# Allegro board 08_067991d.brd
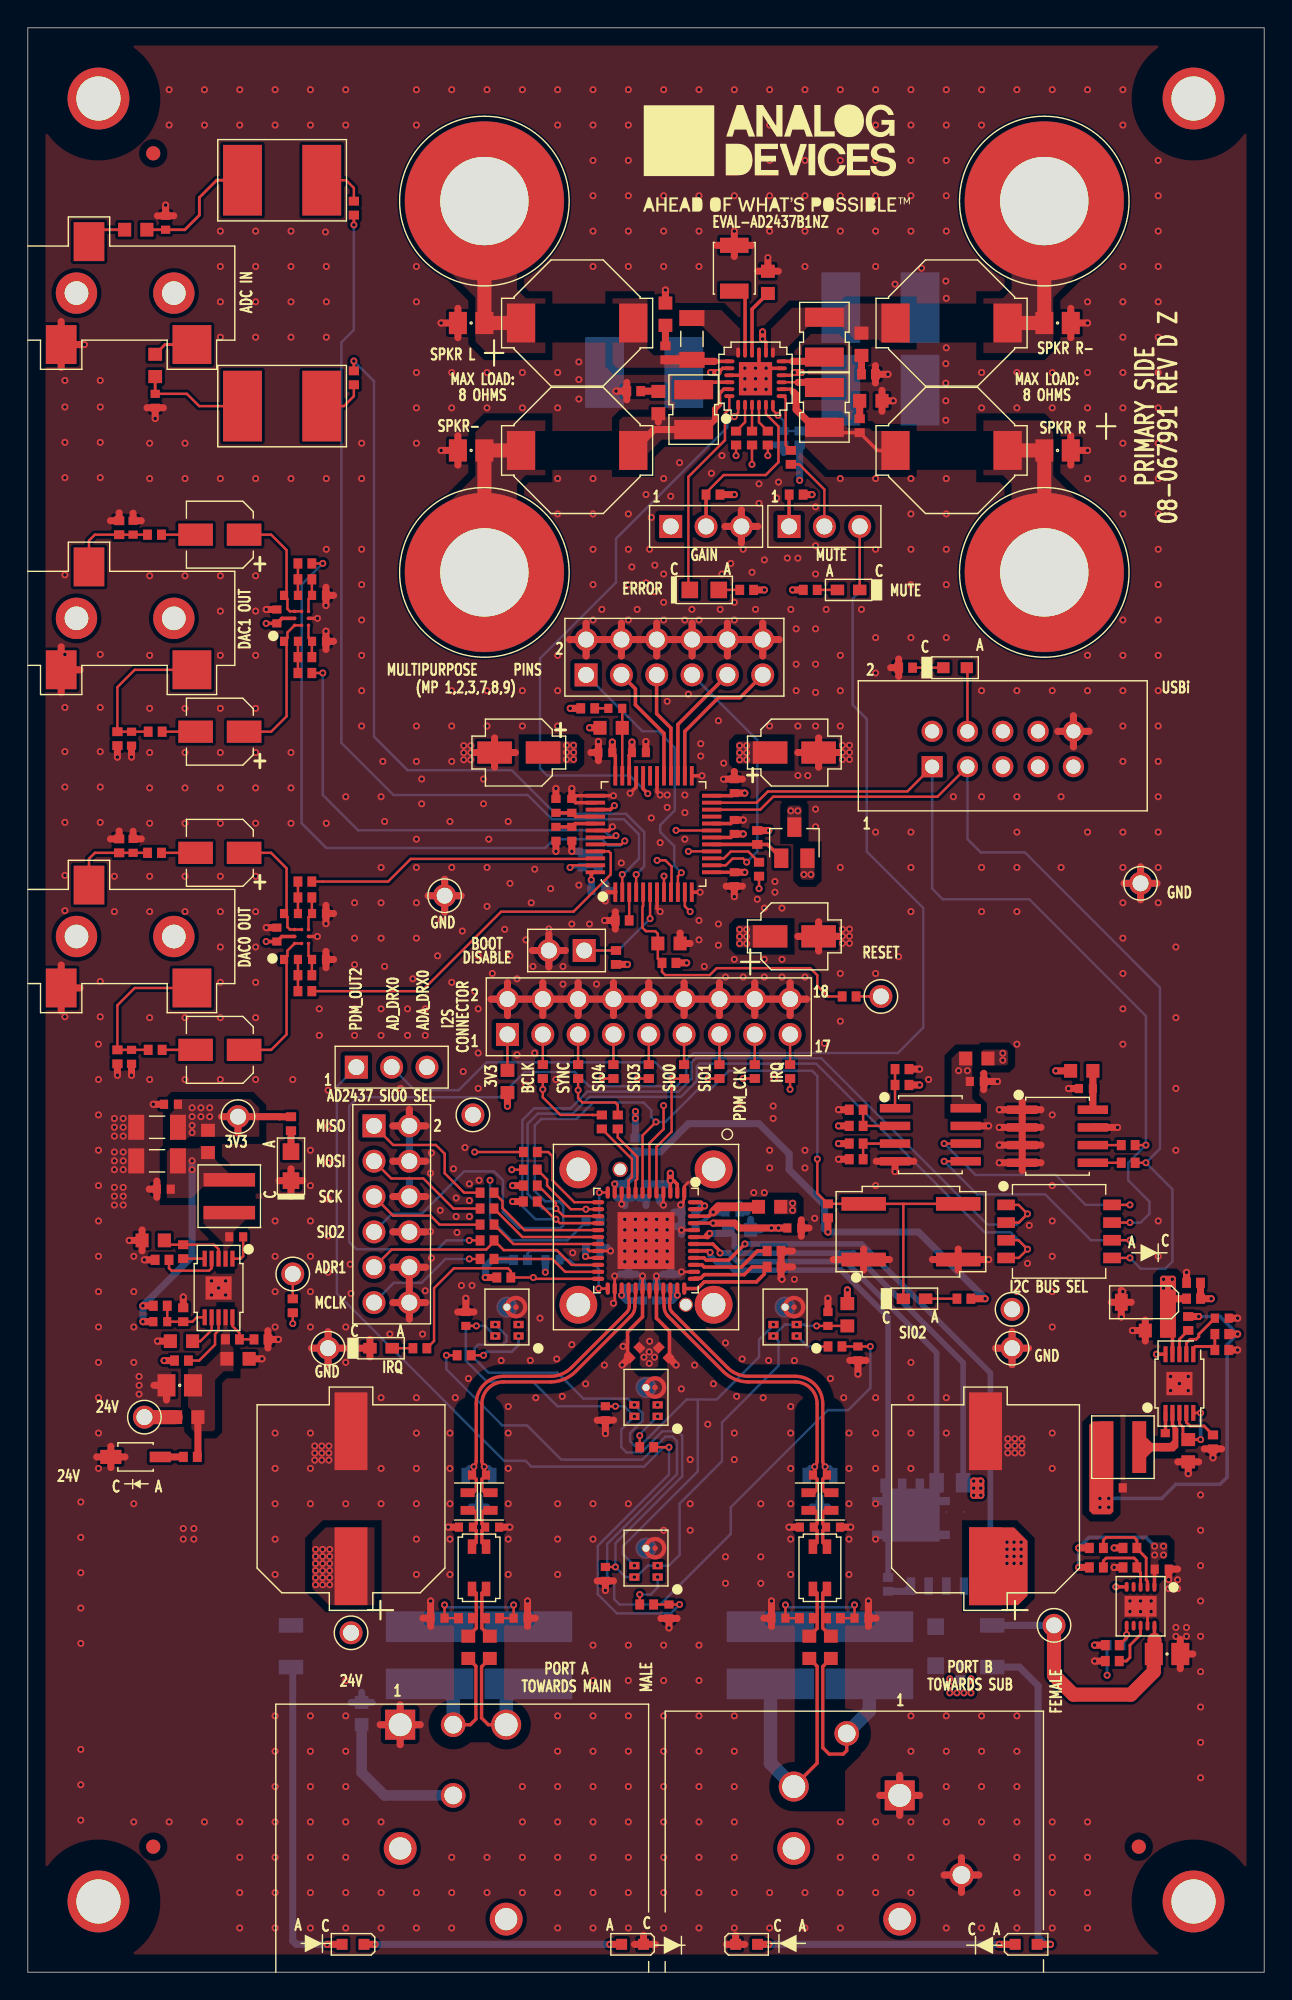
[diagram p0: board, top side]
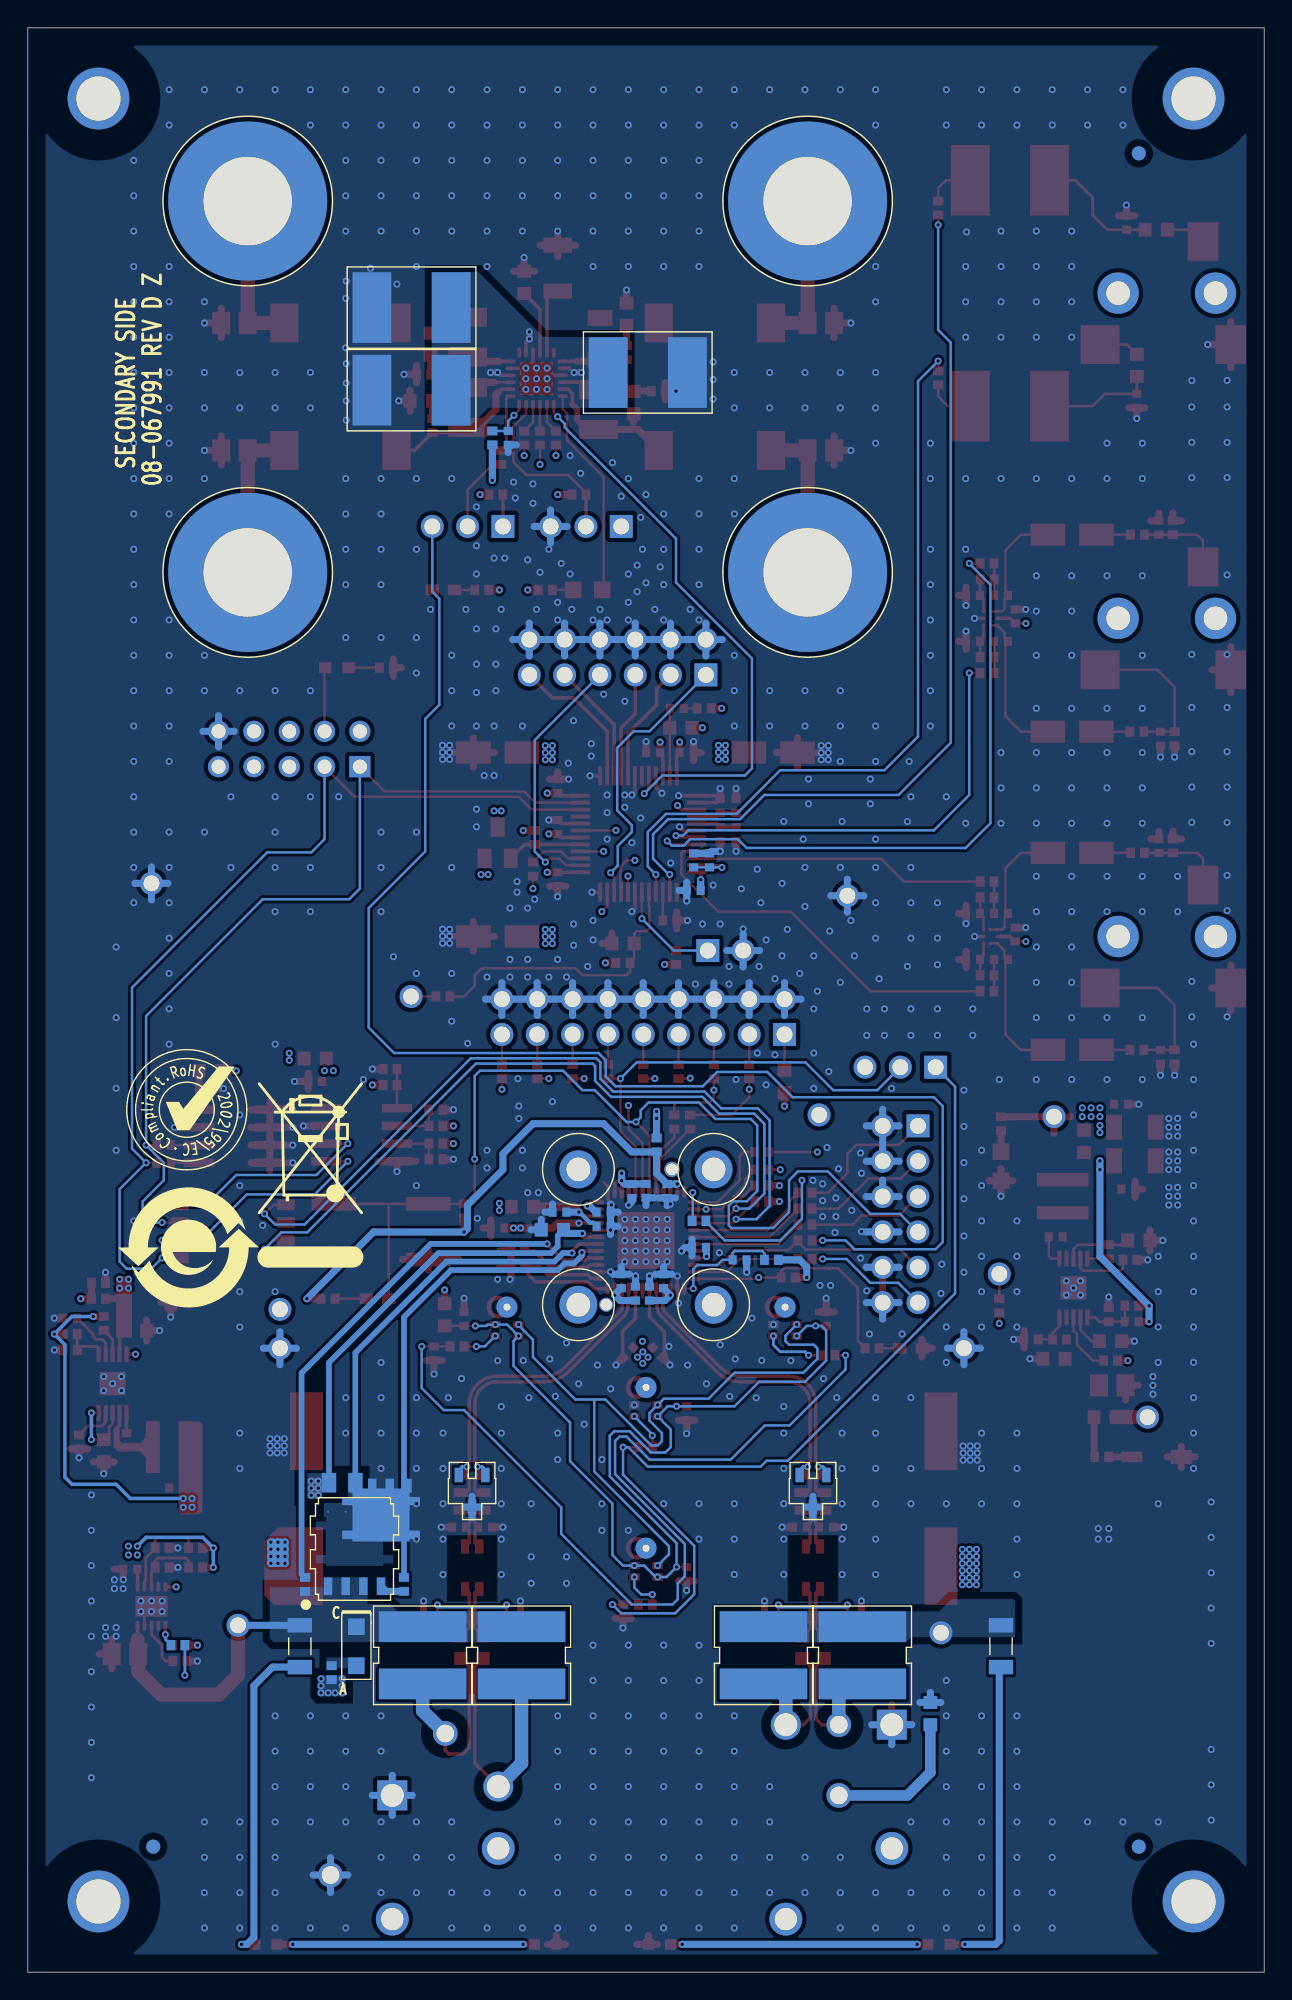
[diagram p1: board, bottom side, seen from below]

Outline 88.9 x 139.7 mm; copper layers: TOP, L2_GND, L3_PWR, L4_PWR, L5_GND, BOTTOM. Coordinates in mm from the lower left corner of the outline.
Outline path: 0,139.7 0,0 88.9,0 88.9,139.7 0,139.7

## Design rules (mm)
constraint set DEFAULT: min track width 0.178
net group APN: nets AN AP
net group BPN: nets BN BP
net group DP1: nets UNNAMED_3_CAP_I7_N1 UNNAMED_3_CAP_I8_N1
net group DP2: nets UNNAMED_3_CAP_I14_N1 UNNAMED_3_CAP_I15_N1
net group DP3: nets UNNAMED_3_CAP_I14_N2 UNNAMED_3_CAP_I15_N2
net group DP4: nets UNNAMED_4_CAP_I2_N1 UNNAMED_4_CAP_I3_N1
net group DP5: nets UNNAMED_4_CAP_I14_N1 UNNAMED_4_CAP_I16_N1
net group DP6: nets UNNAMED_4_CAP_I14_N2 UNNAMED_4_CAP_I16_N2

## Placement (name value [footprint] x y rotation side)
C1  10uF  [C0402]  44.45 56.13 270 bottom
C2  10NF  [C0402]  45.47 56.12 270 bottom
C3  0.1uF  [C0402]  40.64 52.07 0 bottom
C4  0.1uF  [C0402]  47.5 54.61 180 bottom
C5  0.1uF  [C0402]  42.93 56.12 270 bottom
C6  10NF  [C0402]  47.5 53.59 180 bottom
C7  0.1uF  [C0402]  50.67 54.61 0 bottom
C8  0.1uF  [C0603]  51.18 53.34 180 bottom
C9  10uF  [C0402]  55.12 53.47 0 top
C10  0.1uF  [C0402]  45.22 48.76 270 bottom
C11  10NF  [C0402]  45.72 44.52 315 top
C12  4.7uF  [C0402]  46.23 49.65 270 bottom
C13  0.1uF  [C0402]  43.62 44.52 225 top
C14  0.1uF  [C0402]  44.2 48.76 90 bottom
C15  4.7uF  [C0402]  43.18 49.65 90 bottom
C16  0.1uF  [C0402]  68.24 64 0 top
C17  12pF  [C0402]  32.44 35.72 180 top
C18  27pF  [C0402]  33.39 31.98 0 top
C19  27pF  [C0402]  31.5 31.98 180 top
C20  0.033uF  [C0402]  35.43 25.43 180 top
C21  0.033uF  [C0402]  29.46 25.43 180 top
C22  0.01uF  [C0603]  33.22 23.34 270 top
C23  0.01uF  [C0603]  31.67 23.34 270 top
C24  0.01uF  [C0603]  57.74 23.34 270 top
C25  12pF  [C0402]  56.96 35.72 0 top
C26  27pF  [C0402]  56.01 31.98 180 top
C27  27pF  [C0402]  57.9 31.98 0 top
C28  0.033uF  [C0402]  53.97 25.43 0 top
C29  0.033uF  [C0402]  59.94 25.43 0 top
C30  0.01uF  [C0603]  56.19 23.34 270 top
C31  3.3UF  [C1210H110]  47.88 112.27 270 top
C32  330uF  [CPLSMSQ512H650]  23.24 34.01 90 top
C33  330uF  [CPLSMSQ512H650]  68.86 34.01 90 top
C34  3.3UF  [C1210H110]  57.28 112.43 90 top
C35  10uF  [C2220-1]  44.32 114.94 180 bottom
C36  0.1uF  [C0402]  41.53 40.16 90 top
C37  0.1uF  [C0402]  57.53 46.93 270 top
C38  0.1uF  [C0402]  31.5 46.93 270 top
C39  0.1uF  [C0402]  41.53 28.61 270 top
C40  33pF  [C0402]  59.69 44.46 90 top
C41  33pF  [C0402]  46.1 25.92 90 top
C42  1uF  [C0603]  81.15 46.1 0 top
C43  150pF  [C0402]  20.94 76.06 0 top
C44  150pF  [C0402]  20.94 72.76 0 top
C45  470pF  [C0402]  18.92 76.06 180 top
C46  470pF  [C0402]  18.92 72.76 180 top
C47  100pF  [C0402]  9.91 125.69 90 top
C48  100pF  [C0402]  9.16 112.9 270 top
C49  10uF  [C2220-1]  18.28 128.75 180 top
C50  10uF  [C2220-1]  18.28 112.52 180 top
C51  47uF  [CPLSMSQ169H240]  13.81 80.42 180 top
C52  47uF  [CPLSMSQ169H240]  13.81 66.27 180 top
C53  1uF  [C0603]  83.44 37.46 270 top
C54  2.2NF  [C0402]  7.57 80.92 90 top
C55  2.2NF  [C0402]  7.46 65.77 270 top
C56  0.1uF  [C0402]  17.91 74.55 270 top
C57  150pF  [C0402]  20.94 98.92 0 top
C58  150pF  [C0402]  20.94 95.62 0 top
C59  470pF  [C0402]  18.92 98.92 180 top
C60  470pF  [C0402]  18.92 95.62 180 top
C61  47uF  [CPLSMSQ169H240]  13.81 103.28 180 top
C62  47uF  [CPLSMSQ169H240]  13.81 89.13 180 top
C63  0.1uF  [C0402]  17.91 97.41 270 top
C64  2.2NF  [C0402]  7.57 103.78 90 top
C65  2.2NF  [C0402]  7.46 88.63 270 top
C66  10uF  [C2220-1]  61.31 113.66 0 bottom
C67  3.3UF  [C1210H110]  57.28 117.47 270 top
C68  680pF  [C0603]  45.34 112.78 270 top
C69  680pF  [C0603]  45.85 119.13 90 top
C70  3.3uF  [C1206]  47.75 117.35 270 top
C71  680pF  [C0603]  59.94 116.96 90 top
C72  680pF  [C0603]  60.62 112.9 0 top
C73  10UF  [C1210-2]  50.8 122.43 270 top
C74  10uF  [C2220-1]  61.31 119.6 180 bottom
C75  0.68uF  [C0805H60]  31.88 109.34 180 top
C76  0.68uF  [C0805H60]  31.88 118.49 0 top
C77  0.68uF  [C0805H60]  74.04 118.49 0 top
C78  0.68uF  [C0805H60]  74.04 109.34 180 top
C79  0.1uF  [C0603]  53.21 121.41 90 top
C80  1uF  [C0603]  46.1 73.91 180 top
C81  0.1uF  [C0402]  37.72 51.18 180 bottom
C82  10NF  [C0402]  85.85 46.99 0 top
C83  10UF  [CPLSMSQ169H217]  55.12 87.63 0 top
C84  10UF  [CPLSMSQ169H217]  35.31 87.63 180 top
C85  0.1uF  [C0402]  41.02 79.88 90 bottom
C86  0.1uF  [C0402]  50.8 82.28 90 top
C87  10uF  [C0402]  39.88 79.88 90 bottom
C88  0.1uF  [C0402]  41.02 77.72 0 bottom
C89  0.1uF  [C0402]  39.12 83.8 90 top
C90  0.1uF  [C0402]  41.53 87.63 180 top
C91  10uF  [C0402]  37.97 83.8 90 top
C92  0.1uF  [C0402]  43.94 87.63 0 top
C93  10UF  [CPLSMSQ169H217]  55.12 74.42 0 top
C94  0.1uF  [C0402]  50.8 78.53 270 top
C95  0.056uF  [C0402]  42.24 90.8 180 top
C96  0.1uF  [C0402]  50.8 85.22 90 top
C97  3.3NF  [C0603]  41.94 89.41 180 top
C98  10uF  [C0402]  37.97 81.79 270 top
C99  0.1uF  [C0402]  39.12 81.79 270 top
C100  0.1uF  [C0402]  76.08 63.49 0 top
C101  4.7uF  [C0805H60]  10.92 42.16 180 top
C102  0.1uF  [C0603]  15.11 44.07 0 top
C103  1uF  [C0603]  9.02 52.58 180 top
C104  0.01uF  [C0603]  11.05 45.34 0 top
C105  0.1uF  [C0402]  14.99 52.83 0 top
C106  10uF  [C0402]  9.78 56.26 180 top
C107  10pF  [C0402]  9.53 46.74 0 top
C108  22uF  [C1206]  9.29 58.29 180 top
C109  22uF  [C1206]  9.29 60.71 180 top
C110  0.1uF  [C0402]  10.29 62.36 180 top
C114  0.1uF  [C0402]  81.79 38.23 270 top
C115  10uF  [C0402]  78.23 34.8 0 top
C116  1uF  [C0402]  81.53 28.96 0 top
C117  4.7uF  [C0805H60]  81.91 22.86 180 top
C118  0.1uF  [C0402]  54.36 110.24 270 bottom
C123  0.01uF  [C0603]  24 18.58 270 bottom
D1  PMEG6010CEH,115  [SOD123F]  65.28 23.42 270 bottom
D2  BZT52C27-7-F  [SOD123-2]  80.26 48.13 180 top
D4  TPD2E2U06QDBZRQ1  [SOT23_B]  56.96 34.57 0 bottom
D6  TPD2E2U06QDBZRQ1  [SOT23_B]  32.44 34.57 0 bottom
DS1  SML-LXT0805GW-TR  [LXT0805]  18.92 57.91 90 top
DS2  APT1608LVBC/D  [LED0603]  25.4 44.83 0 top
DS3  APT1608LVBC/D  [LED0603]  63.75 48.39 0 top
DS4  LB L293-N1N2-25-Z(blue)  [LED0603-2]  23.39 2 180 top
DS5  SML-E12M8WT86  [LED0603_A]  66.67 93.73 0 top
DS6  APT1608LVBC/D  [LED0603]  59.02 99.31 180 top
DS8  LB L293-N1N2-25-Z(blue)  [LED0603-2]  43.49 2 180 top
DS9  LB L293-N1N2-25-Z(blue)  [LED0603-2]  71.78 2 0 top
DS10  CMD28-21VGC/TR8  [LEDCMD28-21B]  7.75 37.02 0 top
DS11  SML-LXT0805YW-TR  [LXT0805]  48.64 99.31 0 top
DS12  LB L293-N1N2-25-Z(blue)  [LED0603-2]  51.68 2 0 top
E1  600OHMS  [L0603]  34.49 64 270 top
E3  600OHMS  [L0603]  53.34 54.99 180 top
E4  600OHMS  [L0603]  68.24 65.65 180 top
E5  600OHMS  [L0603]  58.93 47.23 90 top
E9  600OHMS  [L0603]  7.76 125.19 0 top
E10  600OHMS  [L0603]  9.16 115.44 270 top
E11  600OHMS  [L0603]  75.78 64.76 0 top
E12  470OHM AT 100MEGHZ  [L0603]  12.95 59.69 90 top
E14  600OHMS  [L0603]  11.43 39.88 180 top
FL1  ACT1210L-101-2P-TL00  [FLSML154W98H98]  32.44 29.05 270 top
FL2  ACT1210L-101-2P-TL00  [FLSML154W98H98]  56.96 29.05 270 top
JP1  TSW-103-07-G-S  [CNTHMHDR1X3L300W98H343]  23.62 65.02 0 top
JP2  TSW-103-07-G-S  [CNTHMHDR1X3L300W98H343]  46.23 103.88 0 top
JP3  TSW-103-07-G-S  [CNTHMHDR1X3L300W98H343]  54.74 103.88 0 top
L1  180nH  [L7144]  33.27 33.82 270 top
L2  180nH  [L7144]  31.62 33.82 270 top
L3  180nH  [L7144]  56.13 33.82 270 top
L4  180nH  [L7144]  57.78 33.82 270 top
L5  15uH  [INDSUMCDRH8D43]  39.5 109.34 180 top
L6  15uH  [INDSUMCDRH8D43]  39.5 118.49 180 top
L7  4.7uH  [LSMSQ228H118]  36 22.77 90 bottom
L8  4.7uH  [LSMSQ228H118]  28.89 22.77 90 bottom
L9  15uH  [INDSUMCDRH8D43]  66.42 118.49 0 top
L10  15uH  [INDSUMCDRH8D43]  66.42 109.34 0 top
L11  4.7uH  [LSMSQ228H118]  53.4 22.77 90 bottom
L12  4.7uH  [LSMSQ228H118]  60.51 22.77 90 bottom
L13  10uH  [LSMSQ157H161]  14.49 55.75 90 top
L14  10uH  [LSMSQ157H161]  78.74 37.72 180 top
NOREF  -  []  -105.41 -135.39 0 top
NOREF#2  -  [unnamed#2]  5.08 5.08 0 top
NOREF#3  -  []  0 0 0 top
NOREF#4  -  [unnamed#2]  49.31 57.68 270 top
NOREF#5  -  [unnamed#2]  39.59 57.68 270 top
NOREF#6  -  []  -105.41 -135.39 0 top
NOREF#7  -  [unnamed#2]  39.59 47.96 270 top
NOREF#8  -  []  69.91 130.99 0 top
NOREF#9  -  [unnamed#2]  79.88 9.02 180 top
NOREF#10  -  []  15.88 210.95 0 top
NOREF#11  -  []  88.9 0 90 top
NOREF#12  -  []  -44.45 235.45 0 top
NOREF#13  -  []  88.9 0 0 top
NOREF#14  -  [unnamed#2]  9.02 9.02 90 top
NOREF#15  -  []  -105.41 -135.39 0 top
NOREF#16  -  []  -12.95 94.11 0 top
NOREF#17  -  []  -85.28 13.58 0 top
NOREF#18  -  []  15.75 206.76 0 top
NOREF#19  -  []  0 139.7 0 top
NOREF#20  -  []  5.08 5.08 0 top
NOREF#21  -  [unnamed#2]  49.31 47.96 270 top
NOREF#22  -  []  0 0 0 top
NOREF#23  -  []  45.97 41.27 0 top
NOREF#24  -  [unnamed#2]  83.82 134.62 0 top
NOREF#25  -  [unnamed#2]  83.82 5.08 0 top
NOREF#26  -  []  0 139.7 0 top
NOREF#27  -  []  15.59 15.24 0 top
NOREF#28  -  []  81.66 19.93 0 top
NOREF#29  -  []  53.86 130.31 0 top
NOREF#30  -  []  164.72 123.94 0 top
NOREF#31  -  [unnamed#2]  47.31 47.96 270 top
NOREF#32  -  [unnamed#2]  9.02 130.68 0 top
NOREF#33  -  []  27.79 183.9 0 top
NOREF#34  -  [unnamed#2]  42.59 57.68 270 top
NOREF#35  -  []  153.42 178.93 0 top
NOREF#36  -  []  -105.41 -135.39 0 top
NOREF#37  -  []  5.08 5.08 0 top
NOREF#38  -  [unnamed#2]  5.08 134.62 0 top
NOREF#39  -  []  275.59 329.43 0 top
NOREF#40  -  []  77.34 52.07 180 bottom
NOREF#41  -  [unnamed#2]  9.02 9.02 270 bottom
NOREF#42  -  []  77.47 61.97 180 bottom
NOREF#43  -  []  59.31 67.51 180 bottom
NOREF#44  -  [unnamed#2]  79.88 9.02 0 bottom
NOREF#45  -  [unnamed#2]  9.02 130.68 180 bottom
P1  NC3MAH-LR  [CNNEUTRIK-NC3MAH-LR]  26.78 17.78 0 top
P2  TSW-109-07-G-D  [CNTHMHDR2X9L900W200H343]  34.49 67.37 0 top
P4  SJ-3523-SMT  [CNCUISJ-3523-SMT]  7 120.64 0 top
P5  TSW-106-07-G-D  [CNHDR2X6H330]  40.14 93.21 0 top
P6  SJ-3523-SMT  [CNCUISJ-3523-SMT]  7 74.41 0 top
P7  SJ-3523-SMT  [CNCUISJ-3523-SMT]  7 97.27 0 top
P9  TSW-101-07-G-D  [CNHDR2X1H428]  40 73.41 90 top
P10  N2510-6002-RB  [CN3MN2510-6002RB]  65.02 86.61 0 top
P13  NC3FAH2-LR-DAE  [CNNEUTRIK-NC3FAH2]  62.69 12.7 180 top
P15  TSW-106-07-G-D  [CNHDR2X6H330]  24.89 60.81 270 top
P16  111-2223-001  [CNEMERSON111-2223-001]  32.83 100.57 90 top
P17  111-2223-001  [CNEMERSON111-2223-001]  32.83 127.25 90 top
P18  111-2223-001  [CNEMERSON111-2223-001]  73.09 127.25 90 top
P19  111-2223-001  [CNEMERSON111-2223-001]  73.09 100.57 90 top
Q1  DMTH8012LPSQ-13  [POWERDI5060-8]  65.41 30.4 180 bottom
Q2  ZXTP25040DFLTA  [SOT23]  55.12 81.15 0 top
R1  0  [R0402]  37.03 64.71 270 top
R2  0  [R0402]  39.57 64.71 270 top
R3  0  [R0402]  42.11 64.71 270 top
R4  0  [R0402]  44.65 64.71 270 top
R5  0  [R0402]  47.19 64.71 270 top
R6  0  [R0402]  49.73 64.71 270 top
R7  0  [R0402]  52.27 64.71 270 top
R8  0  [R0402]  54.81 64.71 270 top
R9  49.9  [R0402]  42.42 61.09 270 top
R10  49.9  [R0402]  41.27 61.09 270 top
R11  49.9  [R0402]  33.02 51.24 0 top
R12  49.9  [R0402]  40.64 53.98 0 bottom
R14  49.9  [R0402]  36.13 57.66 0 top
R15  49.9  [R0402]  36.13 58.93 0 top
R16  330  [R0402]  18.92 60.96 270 top
R17  10K  [R0402]  34.23 49.91 0 top
R18  100K  [R0402]  53.66 50.67 0 top
R19  100K  [R0402]  53.66 51.82 0 top
R20  3.32K  [R0402]  28.19 44.83 180 top
R21  3.32K  [R0402]  67.31 48.39 180 top
R22  10K  [R0402]  62.86 63.74 180 top
R23  10K  [R0402]  62.86 64.89 0 top
R24  10K  [R0402]  59.56 60.8 0 top
R25  10K  [R0402]  59.56 61.97 180 top
R26  10K  [R0402]  57.53 54.7 90 top
R27  10K  [R0402]  59.56 59.53 0 top
R28  10K  [R0402]  59.56 58.41 180 top
R29  113  [R0402]  33.42 25.43 0 top
R30  113  [R0402]  31.47 25.43 0 top
R31  113  [R0402]  55.98 25.43 180 top
R32  113  [R0402]  57.93 25.43 180 top
R33  0  [R0402]  61.85 27.86 270 bottom
R34  0  [R0402]  68.97 27.86 270 bottom
R35  0.05  [R0805]  66.3 35.17 180 bottom
R36  1.78K  [R1206]  69.34 23.42 90 bottom
R37  33  [R0402]  58.04 44.96 0 top
R38  33  [R0402]  31.37 44.32 180 top
R39  33  [R0402]  44.5 26.42 0 top
R40  33  [R0402]  44.5 37.72 0 top
R41  4.75K  [R0402]  19.92 78.36 180 top
R42  4.75K  [R0402]  19.92 70.48 180 top
R43  4.75K  [R0402]  19.92 77.22 0 top
R44  4.75K  [R0402]  19.92 71.63 0 top
R45  18.2K  [R0402]  23.44 126.75 270 top
R46  18.2K  [R0402]  23.44 114.55 90 top
R47  604  [R0402]  9.11 80.42 180 top
R48  604  [R0402]  9.16 66.27 180 top
R49  49.9K  [R0402]  6.57 80.92 90 top
R50  49.9K  [R0402]  6.44 65.77 270 top
R51  4.75K  [R0402]  19.92 101.22 180 top
R52  4.75K  [R0402]  19.92 93.34 180 top
R53  4.75K  [R0402]  19.92 100.08 0 top
R54  4.75K  [R0402]  19.92 94.49 0 top
R55  604  [R0402]  9.11 103.28 180 top
R56  604  [R0402]  9.16 89.13 180 top
R57  49.9K  [R0402]  6.57 103.78 90 top
R58  49.9K  [R0402]  6.44 88.63 270 top
R59  0  [R0402]  53.21 110.23 90 top
R60  5.6  [R0402]  43.57 113.6 0 top
R61  5.6  [R0402]  45.85 116.35 90 top
R62  5.6  [R0402]  60.44 114.81 180 top
R63  47K  [R0402]  49.27 106.16 180 top
R64  330  [R0402]  51.69 99.31 180 top
R65  1K  [R0402]  55.24 106.16 180 top
R66  0  [R0402]  54.86 108.84 90 top
R67  0  [R0402]  50.93 110.23 90 top
R68  0  [R0402]  52.07 110.23 90 top
R69  18.2K  [R0402]  42.74 75.56 0 top
R70  49.9  [R0402]  52.58 79.25 90 top
R71  475  [R0402]  40.26 90.8 180 top
R72  1K  [R0402]  52.45 81.53 90 top
R73  10K  [R0402]  42.29 72.91 270 top
R74  0  [R0402]  79.12 59.43 0 top
R75  0  [R0402]  79.12 58.16 0 top
R76  5.6  [R0402]  59.82 111.11 90 top
R77  1K  [R0402]  63.12 93.73 180 top
R78  2K  [R0402]  36.13 56.52 0 top
R79  162K  [R0402]  14.72 45.47 180 top
R80  10K  [R0402]  16.76 45.47 0 top
R81  0  [R0402]  11.18 51.77 270 top
R82  71.5K  [R0402]  9.65 51.18 180 top
R83  10K  [R0402]  11.05 43.94 0 top
R84  1MEG  [R0402]  9.53 47.88 0 top
R85  309K  [R0402]  11.18 47.24 270 top
R86  2K  [R0402]  36.13 55.37 0 top
R87  100  [R0402]  19.05 47.88 90 top
R88  100  [R0402]  59.05 70.1 0 top
R91  1.78K  [R1206]  18.92 23.42 90 bottom
R95  3.32K  [R0402]  56.26 99.31 0 top
R96  100  [R0402]  67.06 21.52 90 bottom
R97  10K  [R0402]  35.43 51.18 0 bottom
R98  10K  [R0402]  46.1 72.52 0 top
R99  10K  [R0402]  55.5 110.24 90 bottom
R100  0  [R0402]  33.02 56.01 180 top
R101  0  [R0402]  33.02 54.86 180 top
R102  0  [R0402]  33.02 53.71 180 top
R103  0  [R0402]  33.02 52.58 180 top
R104  0  [R0402]  43.69 59.44 270 bottom
R105  100K  [R0402]  83.82 48.39 0 top
R106  10K  [R0402]  83.82 49.53 180 top
R107  18.2K  [R0402]  85.22 38.1 90 top
R108  100K  [R0402]  85.85 45.85 180 top
R109  18.7K  [R0402]  85.85 44.7 180 top
R110  100K  [R0402]  83.44 46.61 270 top
R111  2.2MEG  [R0402]  76.83 30.48 180 top
R112  1.5MEG  [R0402]  79.25 30.48 0 top
R113  2.2MEG  [R0402]  76.83 29.08 180 top
R114  499K  [R0402]  79.25 29.08 0 top
R115  10K  [R0402]  77.98 23.49 0 top
R116  3.01K  [R0402]  77.98 22.35 0 top
R117  10K  [R0402]  78.11 23.49 180 bottom
R151  2.4K  [R0402]  11.68 37.02 180 top
S1  TDA04H0SB1  [SWSMDIP8H91]  74.15 53.22 270 top
S2  EVQQ2K03W  [SWSML260W236H130]  63.5 53.2 0 top
TP1  TESTPAD  [TPC65D45]  23.24 24.38 0 top
TP2  TESTPAD  [TPC65D45]  8.38 39.88 0 top
TP3  TESTPAD  [TPC65D45]  32 61.59 0 top
TP4  TESTPAD  [TPC65D45]  70.77 47.62 0 top
TP5  TESTPAD  [TPC65D45]  21.59 44.83 0 top
TP6  TESTPAD  [TPC65D45]  70.77 44.83 0 top
TP7  TESTPAD  [TPC65D45]  29.97 77.34 0 top
TP8  TESTPAD  [TPC65D45]  80.01 78.23 0 top
TP9  TESTPAD  [TPC65D45]  15.11 61.47 270 top
TP10  TESTPAD  [TPC65D45]  19.05 50.16 0 top
TP11  TESTPAD  [TPC65D45]  73.79 24.92 0 top
TP12  TESTPAD  [TPC65D45]  61.34 70.1 0 top
U1  MMICT3902-00-012  [LGA_CAV5_MEMS]  54.45 47.07 90 top
U2  MMICT3902-00-012  [LGA_CAV5_MEMS]  34.45 47.07 90 top
U3  MMICT3902-00-012  [LGA_CAV5_MEMS]  44.45 29.75 90 top
U4  MMICT3902-00-012  [LGA_CAV5_MEMS]  44.45 41.3 90 top
U5  LT8609EMSE#TRPBF  [MSOP10_PAD1_88X1_68]  13.72 49.16 180 top
U7  AD8606ACBZ  [WLCSP8]  19.68 74.41 0 top
U8  LT8606IMSE#PBF  [MSOP10_PAD1_88X1_68]  82.8 42.29 0 top
U9  AD8606ACBZ  [WLCSP8]  19.68 97.27 0 top
U10  MAX17612AATB+  [DFN10_3X3_PAD2_3X1_5]  80.01 26.29 180 top
U11  AD2437  [QFN48_7X7_PAD4_1X4_1]  44.45 52.57 180 top
U12  ADAU1701JSTZ  [48LQFP]  44.99 81.78 0 top
U14  M24512-RMN6TP  [SO8]  64.9 60.17 270 top
U15  M24512-RMN6TP  [SO8]  74.04 60.06 270 top
U16  BD28623MUV-E2  [QFN24_4X4_PAD2_4X2_4]  52.32 114.49 0 top

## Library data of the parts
C1 C9 C87 C91 C98 C106 C115 = CAP: User Part Number: UPN; Tolerance: 20; alternate symbols: (C0402L); part number: CAP_SM-10UF,10V,20,E020928,C0402; tolerance: 20
C2 C6 C11 C82 = CAP: User Part Number: UPN; Tolerance: 10; alternate symbols: (C0402L); part number: CAP_SM-10NF,25V,10,E046235,C0402; tolerance: 10
C3-C5 C7 C10 C13 C14 C16 C36-C39 C56 C63 C81 C85 C86 C88-C90 C92 C94 C96 C99 C100 C105 C110 C114 C118 = CAP: User Part Number: UPN; Tolerance: 10; alternate symbols: (C0402L); part number: CAP_SM-0.1UF,25V,10,E025708,C0402; tolerance: 10
C8 C79 C102 = CAP: User Part Number: UPN; Tolerance: 10; alternate symbols: (C0603L); part number: CAP_SM-0.1UF,50V,10,E011865,C0603; tolerance: 10
C12 C15 = CAP: User Part Number: UPN; Tolerance: 20; alternate symbols: (C0402L); part number: CAP_SM-4.7UF,6.3V,20,E014207,C0402; tolerance: 20
C17 C25 = CAP: User Part Number: UPN; Tolerance: 5; alternate symbols: (C0402L); part number: CAP_SM-12PF,50V,5,E034633,C0402; tolerance: 5
C18 C19 C26 C27 = CAP: User Part Number: UPN; Tolerance: 5; alternate symbols: (C0402L); part number: CAP_SM-27PF,50V,5,E033384,C0402; tolerance: 5
C20 C21 C28 C29 = CAP: User Part Number: UPN; Tolerance: 10; alternate symbols: (C0402L); part number: CAP_SM-0.033UF,50V,10,E019776,C0402; tolerance: 10
C22-C24 C30 C104 = CAP: User Part Number: UPN; Tolerance: 10; alternate symbols: (C0603L); part number: CAP_SM-0.01UF,50V,10,E000421,C0603; tolerance: 10
C31 C34 C67 = CAP: Tolerance: 20; User Part Number: UPN; alternate symbols: (); part number: CAP_SM-3.3UF,50V,20,E042926,C1210H110; tolerance: 20
C32 C33 = CAPP: User Part Number: UPN; Tolerance: 20; alternate symbols: (); part number: CAPP_SM-330UF,63V,20,E040098,CPLSMSQ512H650; tolerance: 20
C35 C49 C50 C66 C74 = CAP: Tolerance: 10; User Part Number: UPN; alternate symbols: (); part number: CAP_SM-10UF,50V,10,E007065,C2220-1; tolerance: 10
C40 C41 = CAP: User Part Number: UPN; Tolerance: 5; alternate symbols: (C0402L); part number: CAP_SM-33PF,50V,5,E035965,C0402; tolerance: 5
C42 C53 C80 C103 = CAP: User Part Number: UPN; Tolerance: 10; alternate symbols: (C0603L); part number: CAP_SM-1UF,35V,10,E020621,C0603; tolerance: 10
C43 C44 C57 C58 = CAP: User Part Number: UPN; Tolerance: 10; alternate symbols: (C0402L); part number: CAP_SM-150PF,50V,10,E033997,C0402; tolerance: 10
C45 C46 C59 C60 = CAP: User Part Number: UPN; Tolerance: 10; alternate symbols: (C0402L); part number: CAP_SM-470PF,25V,10,E012313,C0402; tolerance: 10
C47 C48 = CAP: User Part Number: UPN; Tolerance: 5; alternate symbols: (C0402L); part number: CAP_SM-100PF,50V,5,E022402,C0402; tolerance: 5
C51 C52 C61 C62 = CAPP: Tolerance: 20; User Part Number: UPN; alternate symbols: (); part number: CAPP_SM-47UF,6.3V,20,E014836,CPLSMSQ169H240; tolerance: 20
C54 C55 C64 C65 = CAP: User Part Number: UPN; Tolerance: 20; alternate symbols: (C0402L); part number: CAP_SM-2.2NF,25V,20,E042791,C0402; tolerance: 20
C68 C69 C71 C72 = CAP: User Part Number: UPN; Tolerance: 5; alternate symbols: (C0603L); part number: CAP_SM-680PF,50V,5,E000431,C0603; tolerance: 5
C70 = CAP: User Part Number: UPN; Tolerance: 10; alternate symbols: (C1206L); part number: CAP_SM-3.3UF,16V,10,E000196,C1206; tolerance: 10
C73 = CAP: Tolerance: 10; User Part Number: UPN; alternate symbols: (C1210H106); part number: CAP_SM-10UF,25V,10,E013830,C1210-2; tolerance: 10
C75-C78 = CAP: Tolerance: 5; User Part Number: UPN; alternate symbols: (); part number: CAP_SM-0.68UF,25V,5,E018577,C0805H60; tolerance: 5
C83 C84 C93 = CAPP: Tolerance: 20; User Part Number: UPN; alternate symbols: (); part number: CAPP_SM-10UF,16V,20,E056431,CPLSMSQ169H217; tolerance: 20
C95 = CAP: User Part Number: UPN; Tolerance: 0.1; alternate symbols: (C0402L); part number: CAP_SM-0.056UF,16V,0.1,E019786,C0402; tolerance: 0.1
C97 = CAP: User Part Number: UPN; Tolerance: 20; alternate symbols: (C0603L); part number: CAP_SM-3.3NF,16V,20,E042849,C0603; tolerance: 20
C101 C117 = CAP: Tolerance: 10; User Part Number: UPN; alternate symbols: (); part number: CAP_SM-4.7UF,35V,10,E026260,C0805H60; tolerance: 10
C107 = CAP: User Part Number: UPN; Tolerance: 5; alternate symbols: (C0402L); part number: CAP_SM-10PF,50V,5,E007982,C0402; tolerance: 5
C108 C109 = CAP: User Part Number: UPN; Tolerance: 10; alternate symbols: (C1206L); part number: CAP_SM-22UF,16V,10,E026209,C1206; tolerance: 10
C116 = CAP: User Part Number: UPN; Tolerance: 20; alternate symbols: (C0402L); part number: CAP_SM-1UF,16V,20,E020695,C0402; tolerance: 20
C123 = CAP: User Part Number: UPN; Tolerance: 10; alternate symbols: (C0603L); part number: CAP_SM-0.01UF,100V,10,E032297,C0603; tolerance: 10
D1 = DIOSCHOTTKY: Tolerance: N/A; User Part Number: UPN; alternate symbols: (); part number: DIOSCHOTTKY_SM-PMEG6010CEH,115,60V,N/A,E052090,SOD123F; tolerance: N/A
D2 = DIOZNR: User Part Number: UPN; Tolerance: 7; alternate symbols: (); part number: DIOZNR_SM-BZT52C27-7-F,27V,7,E026666,SOD123-2; tolerance: 7
D4 D6 = DIOZNR3P_V7: User Part Number: UPN; Tolerance: N/A; alternate symbols: (); part number: DIOZNR3P_V7_SM-TPD2E2U06QDBZRQ1,5.5V,N/A,E050894,SOT23_B; tolerance: N/A
DS1 = DIOLED: Tolerance: N/A; User Part Number: UPN; alternate symbols: (); part number: DIOLED_SM-SML-LXT0805GW-TR,N/A,N/A,E005318,LXT0805; tolerance: N/A
DS2 DS3 DS6 = DIOLED: Tolerance: N/A; User Part Number: UPN; alternate symbols: (); part number: DIOLED_SM-APT1608LVBC/D,2.65V,N/A,E039384,LED0603; tolerance: N/A
DS4 DS8 DS9 DS12 = DIOLED: Tolerance: N/A; User Part Number: UPN; alternate symbols: (); part number: DIOLED_SM-LB L293-N1N2-25-Z(BLUE),3.1V,N/A,E014128,LED0603-2; tolerance: N/A
DS5 = DIOLED: User Part Number: UPN; Tolerance: N/A; alternate symbols: (); part number: DIOLED_SM-SML-E12M8WT86,2.2V,N/A,E024936,LED0603_A; tolerance: N/A
DS10 = DIOLED: Tolerance: N/A; User Part Number: UPN; alternate symbols: (); part number: DIOLED_SM-CMD28-21VGC/TR8,2.1V,N/A,E001181,LEDCMD28-21B; tolerance: N/A
DS11 = DIOLED: Tolerance: N/A; User Part Number: UPN; alternate symbols: (); part number: DIOLED_SM-SML-LXT0805YW-TR,N/A,N/A,E005351,LXT0805; tolerance: N/A
E1 E3-E5 E9-E11 E14 = FERRITE: User Part Number: UPN; Tolerance: 25; alternate symbols: (L0603L); part number: FERRITE_SM-600OHMS,25,E007179,L0603; tolerance: 25
E12 = FERRITE: User Part Number: UPN; Tolerance: 25; alternate symbols: (L0603L); part number: FERRITE_SM-470OHM AT 100MEGHZ,25,E044359,L0603; tolerance: 25
FL1 FL2 = FLTR4P_V7: User Part Number: UPN; Tolerance: N/A; alternate symbols: (); part number: FLTR4P_V7_SM-ACT1210L-101-2P-TL00,E033324,FLSML154W98H98; tolerance: N/A
JP1-JP3 = CN3P: User Part Number: UPN; Tolerance: N/A; alternate symbols: (); part number: CN3P_TH-TSW-103-07-G-S,E042653,CNTHMHDR1X3L300W98H343; tolerance: N/A
L1-L4 = IND: Tolerance: 5; User Part Number: UPN; alternate symbols: (); part number: IND_SM-180NH,5,E006401,L7144; tolerance: 5
L5 L6 L9 L10 = IND: Tolerance: 30; User Part Number: UPN; alternate symbols: (); part number: IND_SM-15UH,30,E005329,INDSUMCDRH8D43; tolerance: 30
L7 L8 L11 L12 = IND: User Part Number: UPN; Tolerance: 30; alternate symbols: (); part number: IND_SM-4.7UH,30,E013832,LSMSQ228H118; tolerance: 30
L13 L14 = IND: User Part Number: UPN; Tolerance: 20; alternate symbols: (); part number: IND_SM-10UH,20,E016513,LSMSQ157H161; tolerance: 20
P1 = CN3P_1GND: Tolerance: N/A; User Part Number: UPN; alternate symbols: (); part number: CN3P_1GND_TH-NC3MAH-LR,E056795,CNNEUTRIK-NC3MAH-LR; tolerance: N/A
P2 = CN18P_ODD_EVEN: User Part Number: UPN; Tolerance: N/A; alternate symbols: (); part number: CN18P_ODD_EVEN_TH-TSW-109-07-G-D,E029947,CNTHMHDR2X9L900W200H343; tolerance: N/A
P4 P6 P7 = CN3P: Tolerance: N/A; User Part Number: UPN; alternate symbols: (); part number: CN3P_SM-SJ-3523-SMT,E008203,CNCUISJ-3523-SMT; tolerance: N/A
P5 P15 = CN12P: User Part Number: UPN; Tolerance: N/A; alternate symbols: (); part number: CN12P_TH-TSW-106-07-G-D,E016473,CNHDR2X6H330; tolerance: N/A
P9 = CN2P: User Part Number: UPN; Tolerance: N/A; alternate symbols: (); part number: CN2P_TH-TSW-101-07-G-D,E020218,CNHDR2X1H428; tolerance: N/A
P10 = CN10P: Tolerance: N/A; User Part Number: UPN; alternate symbols: (); part number: CN10P_TH-N2510-6002-RB,E005954,CN3MN2510-6002RB; tolerance: N/A
P13 = CN3P_1GND: User Part Number: UPN; Tolerance: N/A; alternate symbols: (); part number: CN3P_1GND_TH-NC3FAH2-LR-DAE,E056794,CNNEUTRIK-NC3FAH2; tolerance: N/A
P16-P19 = CNTP1P: Tolerance: N/A; User Part Number: UPN; alternate symbols: (); part number: CNTP1P_TH-111-2223-001,E015368,CNEMERSON111-2223-001; tolerance: N/A
Q1 = TRANNMOSFET_V15: User Part Number: UPN; Tolerance: N/A; alternate symbols: (); part number: TRANNMOSFET_V15_SM-DMTH8012LPSQ-13,E045036,POWERDI5060-8; tolerance: N/A
Q2 = TRANMMBT3640: User Part Number: UPN; Tolerance: N/A; alternate symbols: (); part number: TRANMMBT3640_SM-ZXTP25040DFLTA,E018084,SOT23; tolerance: N/A
R1-R8 R33 R34 R59 R66-R68 R74 R75 R81 R100-R104 = RES: User Part Number: UPN; Tolerance: JUMPER; alternate symbols: (R0402L,R0402L_ALT); part number: RES_SM-0,E003438,1/10W,JUMPER,R0402; tolerance: JUMPER
R9-R12 R14 R15 R70 = RES: User Part Number: UPN; Tolerance: 1; alternate symbols: (R0402L); part number: RES_SM-49.9,E003750,1/10W,1,R0402; tolerance: 1
R16 R64 = RES: User Part Number: UPN; Tolerance: 5; alternate symbols: (R0402L); part number: RES_SM-330,E003462,1/10W,5,R0402; tolerance: 5
R17 = RES: User Part Number: UPN; Tolerance: 0.1; alternate symbols: (R0402L); part number: RES_SM-10K,E012474,1/16W,0.1,R0402; tolerance: 0.1
R18 R19 R105 R108 R110 = RES: User Part Number: UPN; Tolerance: 5; alternate symbols: (R0402L); part number: RES_SM-100K,E003464,1/10W,5,R0402; tolerance: 5
R20 R21 R95 = RES: User Part Number: UPN; Tolerance: 1; alternate symbols: (R0402L); part number: RES_SM-3.32K,E034634,1/10W,1,R0402; tolerance: 1
R22-R28 R73 R80 R83 R97-R99 R106 R115 R117 = RES: User Part Number: UPN; Tolerance: 1; alternate symbols: (R0402L,R0402L_ALT); part number: RES_SM-10K,E003751,1/10W,1,R0402; tolerance: 1
R29-R32 = RES: User Part Number: UPN; Tolerance: 1; alternate symbols: (R0402L); part number: RES_SM-113,E007888,1/10W,1,R0402; tolerance: 1
R35 = RES: User Part Number: UPN; Tolerance: 1; alternate symbols: (R0805L); part number: RES_SM-0.05,E013377,1/8W,1,R0805; tolerance: 1
R36 R91 = RES: User Part Number: UPN; Tolerance: 1; alternate symbols: (R1206L); part number: RES_SM-1.78K,E003243,1/4W,1,R1206; tolerance: 1
R37-R40 = RES: User Part Number: UPN; Tolerance: 5; alternate symbols: (R0402L); part number: RES_SM-33,E003452,1/10W,5,R0402; tolerance: 5
R41-R44 R51-R54 = RES: User Part Number: UPN; Tolerance: 1; alternate symbols: (R0402L); part number: RES_SM-4.75K,E019642,1/16W,1,R0402; tolerance: 1
R45 R46 R69 R107 = RES: User Part Number: UPN; Tolerance: 1; alternate symbols: (R0402L); part number: RES_SM-18.2K,E010424,1/10W,1,R0402; tolerance: 1
R47 R48 R55 R56 = RES: User Part Number: UPN; Tolerance: 1; alternate symbols: (R0402L); part number: RES_SM-604,E020998,1/10W,1,R0402; tolerance: 1
R49 R50 R57 R58 = RES: User Part Number: UPN; Tolerance: 1; alternate symbols: (R0402L); part number: RES_SM-49.9K,E004901,1/10W,1,R0402; tolerance: 1
R60-R62 R76 = RES: User Part Number: UPN; Tolerance: 5; alternate symbols: (R0402L); part number: RES_SM-5.6,E015599,1/10W,5,R0402; tolerance: 5
R63 = RES: User Part Number: UPN; Tolerance: 1; alternate symbols: (R0402L,R0402L_ALT); part number: RES_SM-47K,E008189,1/10W,1,R0402; tolerance: 1
R65 R72 R77 = RES: User Part Number: UPN; Tolerance: 1; alternate symbols: (R0402L,R0402L_ALT); part number: RES_SM-1K,E003763,1/10W,1,R0402; tolerance: 1
R71 = RES: User Part Number: UPN; Tolerance: 1; alternate symbols: (R0402L); part number: RES_SM-475,E008186,1/10W,1,R0402; tolerance: 1
R78 R86 = RES: User Part Number: UPN; Tolerance: 1; alternate symbols: (R0402L,R0402L_ALT); part number: RES_SM-2K,E003752,1/10W,1,R0402; tolerance: 1
R79 = RES: User Part Number: UPN; Tolerance: 1; alternate symbols: (R0402L); part number: RES_SM-162K,E035428,1/10W,1,R0402; tolerance: 1
R82 = RES: User Part Number: UPN; Tolerance: 1; alternate symbols: (R0402L); part number: RES_SM-71.5K,E019735,1/16W,1,R0402; tolerance: 1
R84 = RES: User Part Number: UPN; Tolerance: 1; alternate symbols: (R0402L); part number: RES_SM-1MEG,E003749,1/10W,1,R0402; tolerance: 1
R85 = RES: User Part Number: UPN; Tolerance: 1; alternate symbols: (R0402L); part number: RES_SM-309K,E033606,1/16W,1,R0402; tolerance: 1
R87 R88 = RES: User Part Number: UPN; Tolerance: 1; alternate symbols: (R0402L); part number: RES_SM-100,E016329,1/10W,1,R0402; tolerance: 1
R96 = RES: User Part Number: UPN; Tolerance: 5; alternate symbols: (R0402L); part number: RES_SM-100,E003443,1/10W,5,R0402; tolerance: 5
R109 = RES: User Part Number: UPN; Tolerance: 1; alternate symbols: (R0402L); part number: RES_SM-18.7K,E010018,1/10W,1,R0402; tolerance: 1
R111 R113 = RES: User Part Number: UPN; Tolerance: 1; alternate symbols: (R0402L); part number: RES_SM-2.2MEG,E059406,1/16W,1,R0402; tolerance: 1
R112 = RES: User Part Number: UPN; Tolerance: 1; alternate symbols: (R0402L); part number: RES_SM-1.5MEG,E034365,1/10W,1,R0402; tolerance: 1
R114 = RES: User Part Number: UPN; Tolerance: 1; alternate symbols: (R0402L); part number: RES_SM-499K,E019889,1/10W,1,R0402; tolerance: 1
R116 = RES: User Part Number: UPN; Tolerance: 1; alternate symbols: (R0402L); part number: RES_SM-3.01K,E027299,1/10W,1,R0402; tolerance: 1
R151 = RES: User Part Number: UPN; Tolerance: 1; alternate symbols: (R0402L); part number: RES_SM-2.4K,E003787,1/16W,1,R0402; tolerance: 1
S1 = SWITCH4: User Part Number: UPN; Tolerance: N/A; alternate symbols: (); part number: SWITCH4_SM-TDA04H0SB1,E017346,SWSMDIP8H91; tolerance: N/A
S2 = SWSPST4PIN_V8: User Part Number: UPN; Tolerance: N/A; alternate symbols: (); part number: SWSPST4PIN_V8_SM-EVQQ2K03W,E023950,SWSML260W236H130; tolerance: N/A
TP1-TP12 = NCTESTPAD: Tolerance: N/A; User Part Number: UPN; alternate symbols: (); part number: NCTESTPAD_TH-TESTPAD,E013404,TPC65D45; tolerance: N/A
U1-U4 = ICT3902: Tolerance: N/A; User Part Number: UPN; alternate symbols: (); part number: ICT3902_SM-MMICT3902-00-012,E056497,LGA_CAV5_MEMS; tolerance: N/A
U5 = ADLT8609: User Part Number: UPN; Tolerance: N/A; alternate symbols: (); part number: ADLT8609_SM-LT8609EMSE#TRPBF,E035643,MSOP10_PAD1_88X1_68; tolerance: N/A
U7 U9 = AD8606: Tolerance: N/A; User Part Number: UPN; alternate symbols: (); part number: AD8606_SM-AD8606ACBZ,E010370,WLCSP8; tolerance: N/A
U8 = ADLT8606_V2: User Part Number: UPN; Tolerance: N/A; alternate symbols: (); part number: ADLT8606_V2_SM-LT8606IMSE#PBF,E035609,MSOP10_PAD1_88X1_68; tolerance: N/A
U10 = ADMAX17612X: User Part Number: UPN; Tolerance: N/A; alternate symbols: (); part number: ADMAX17612X_SM-MAX17612AATB+,E058891,DFN10_3X3_PAD2_3X1_5; tolerance: N/A
U11 = AD243XW: Tolerance: N/A; User Part Number: UPN; alternate symbols: (SKTIRONWOOD_SBT-QFN-4022_QFN48_7X7_PAD4_1X4_1,SKTIRONWOOD_SBT-QFN-4022_QFN48_7X7_PAD4_1X4_1_NPM); part number: AD243XW_SM-AD2437,E049687,QFN48_7X7_PAD4_1X4_1; tolerance: N/A
U12 = ADAU1701: Tolerance: N/A; User Part Number: UPN; alternate symbols: (); part number: ADAU1701_SM-ADAU1701JSTZ,E005147,48LQFP; tolerance: N/A
U14 U15 = ICM24512: Tolerance: N/A; User Part Number: UPN; alternate symbols: (); part number: ICM24512_SM-M24512-RMN6TP,E041427,SO8; tolerance: N/A
U16 = ICBD28623MUV: Tolerance: N/A; User Part Number: UPN; alternate symbols: (); part number: ICBD28623MUV_SM-BD28623MUV-E2,E051667,QFN24_4X4_PAD2_4X2_4; tolerance: N/A

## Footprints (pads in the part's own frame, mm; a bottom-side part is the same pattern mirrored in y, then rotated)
48LQFP
  rect 0.279x1.397 smd: 1(-2.75,-4.182) 2(-2.25,-4.182) 3(-1.75,-4.182) 4(-1.25,-4.182) 5(-0.75,-4.182) 6(-0.25,-4.182) 7(0.25,-4.182) 8(0.75,-4.182) 9(1.25,-4.182) 10(1.75,-4.182) 11(2.25,-4.182) 12(2.75,-4.182) 25(2.75,4.182) 26(2.25,4.182) 27(1.75,4.182) 28(1.25,4.182) 29(0.75,4.182) 30(0.25,4.182) 31(-0.25,4.182) 32(-0.75,4.182) 33(-1.25,4.182) 34(-1.75,4.182) 35(-2.25,4.182) 36(-2.75,4.182)
  rect 1.397x0.279 smd: 13(4.182,-2.75) 14(4.182,-2.25) 15(4.182,-1.75) 16(4.182,-1.25) 17(4.182,-0.75) 18(4.182,-0.25) 19(4.182,0.25) 20(4.182,0.75) 21(4.182,1.25) 22(4.182,1.75) 23(4.182,2.25) 24(4.182,2.75) 37(-4.182,2.75) 38(-4.182,2.25) 39(-4.182,1.75) 40(-4.182,1.25) 41(-4.182,0.75) 42(-4.182,0.25) 43(-4.182,-0.25) 44(-4.182,-0.75) 45(-4.182,-1.25) 46(-4.182,-1.75) 47(-4.182,-2.25) 48(-4.182,-2.75)
C0402
  rect 0.584x0.66 smd: 1(-0.5,0) 2(0.5,0)
C0603
  rect 0.94x0.991 smd: 1(-0.8,0) 2(0.8,0)
C0805H60
  rect 1.295x1.6 smd: 1(-0.953,0) 2(0.953,0)
C1206
  rect 1.143x1.803 smd: 1(-1.5,0) 2(1.5,0)
C1210-2
  rect 1.092x2.057 smd: 1(-1.646,0) 2(1.646,0)
C1210H110
  rect 1.372x2.794 smd: 1(-1.431,0) 2(1.431,0)
C2220-1
  rect 2.794x5.08 smd: 1(-2.85,0) 2(2.85,0)
CN3MN2510-6002RB
  rect 1.524x1.524 hole 1.016: 1(0,0)
  round 1.524 hole 1.016: 2(0,2.54) 3(2.54,0) 4(2.54,2.54) 5(5.08,0) 6(5.08,2.54) 7(7.62,0) 8(7.62,2.54) 9(10.16,0) 10(10.16,2.54)
CNCUISJ-3523-SMT
  round 2.972 hole 1.702 unplated: (-3.5,0) (3.5,0)
  rect 2.21x2.794 smd: 1(-4.6,-3.697) 3(-2.6,3.697)
  rect 2.794x2.794 smd: 2(4.8,-3.697)
CNEMERSON111-2223-001
  round 11.43 hole 6.35: 1(0,0)
CNHDR2X1H428
  rect 1.651x1.651 hole 1.143: 1(0,0)
  round 1.651 hole 1.143: 2(0,2.54)
CNHDR2X6H330
  rect 1.651x1.651 hole 1.143: 1(0,0)
  round 1.651 hole 1.143: 2(0,2.54) 3(2.54,0) 4(2.54,2.54) 5(5.08,0) 6(5.08,2.54) 7(7.62,0) 8(7.62,2.54) 9(10.16,0) 10(10.16,2.54) 11(12.7,0) 12(12.7,2.54)
CNNEUTRIK-NC3FAH2
  round 2.362 hole 1.6 unplated: (0,8.89) (7.62,3.81)
  rect 2.159x2.159 hole 1.651: 1(0,0)
  round 2.159 hole 1.651: 2(7.62,-0.635)
  round 1.778 hole 1.27: 3(3.81,-4.45) GND(-4.44,5.72)
CNNEUTRIK-NC3MAH-LR
  round 2.362 hole 1.6 unplated: (0,-8.89) (7.62,-13.97)
  rect 2.159x2.159 hole 1.651: 1(0,0)
  round 2.159 hole 1.651: 2(7.62,0)
  round 1.778 hole 1.27: 3(3.81,0) GND(3.81,-5.08)
CNTHMHDR1X3L300W98H343
  rect 1.651x1.651 hole 1.143: 1(0,0)
  round 1.651 hole 1.143: 2(2.54,0) 3(5.08,0)
CNTHMHDR2X9L900W200H343
  rect 1.651x1.651 hole 1.143: 1(0,0)
  round 1.651 hole 1.143: 2(0,2.54) 3(2.54,0) 4(2.54,2.54) 5(5.08,0) 6(5.08,2.54) 7(7.62,0) 8(7.62,2.54) 9(10.16,0) 10(10.16,2.54) 11(12.7,0) 12(12.7,2.54) 13(15.24,0) 14(15.24,2.54) 15(17.78,0) 16(17.78,2.54) 17(20.32,0) 18(20.32,2.54)
CPLSMSQ169H217
  rect 2.489x1.6 smd: N(1.745,0) P(-1.745,0)
CPLSMSQ169H240
  rect 2.489x1.6 smd: N(1.745,0) P(-1.745,0)
CPLSMSQ512H650
  rect 5.588x2.362 smd: N(4.85,0) P(-4.85,0)
DFN10_3X3_PAD2_3X1_5
  oval 0.279x0.711 smd: 1(-1,-1.396) 2(-0.5,-1.396) 3(0,-1.396) 4(0.5,-1.396) 5(1,-1.396) 6(1,1.396) 7(0.5,1.396) 8(0,1.396) 9(-0.5,1.396) 10(-1,1.396)
  rect 2.311x1.499 smd: PAD(0,0)
FLSML154W98H98
  rect 1.041x0.61 smd: 1(-1.521,0.505) 2(-1.521,-0.505) 3(1.521,-0.505) 4(1.521,0.505)
INDSUMCDRH8D43
  rect 2.032x2.794 smd: 1(-4.034,0) 2(4.034,0)
L0603
  rect 0.94x0.991 smd: 1(-0.8,0) 2(0.8,0)
L7144
  rect 0.635x1.016 smd: 1(-0.635,0) 2(0.635,0)
LED0603
  rect 0.965x0.762 smd: A(0.8,0) C(-0.8,0)
LED0603-2
  rect 0.787x0.787 smd: A(0.787,0) C(-0.787,0)
LED0603_A
  rect 0.889x0.787 smd: A(0.845,0) C(-0.845,0)
LEDCMD28-21B
  rect 1.524x0.762 smd: A(1.778,0)
  rect 1.524x1.016 smd: C(-1.778,0)
LGA_CAV5_MEMS
  round 0.635 hole 0.508 unplated: (0.71,0)
  rect 0.533x0.737 smd: 1(-1.364,-0.837) 2(-0.542,-0.837) 4(-0.542,0.837) 5(-1.364,0.837)
  custom 0.407x0.407 smd: 3(0.71,-0.65)
LSMSQ157H161
  rect 0.965x3.708 smd: 1(-1.181,0) 2(1.181,0)
LSMSQ228H118
  rect 2.21x6.299 smd: 1(-2.055,0) 2(2.055,0)
LXT0805
  rect 1.194x1.194 smd: A(1.041,0) C(-1.041,0)
MSOP10_PAD1_88X1_68
  rect 0.305x1.143 smd: 1(-1,-2.106) 2(-0.5,-2.106) 3(0,-2.106) 4(0.5,-2.106) 5(1,-2.106) 6(1,2.106) 7(0.5,2.106) 8(0,2.106) 9(-0.5,2.106) 10(-1,2.106)
  rect 1.88x1.676 smd: PAD(0,0)
POWERDI5060-8
  rect 0.61x1.27 smd: 1(-1.905,-2.67) 2(-0.635,-2.67) 3(0.635,-2.67) 4(1.905,-2.67)
  custom 1.13x1.13 smd: 5(1.905,2.797)
  round 0.127 smd: 6(0.635,2.67) 7(-0.635,2.67) 8(-1.905,2.67)
QFN24_4X4_PAD2_4X2_4
  oval 0.279x0.737 smd: 1(-1.25,-1.883) 2(-0.75,-1.883) 3(-0.25,-1.883) 4(0.25,-1.883) 5(0.75,-1.883) 6(1.25,-1.883) 13(1.25,1.883) 14(0.75,1.883) 15(0.25,1.883) 16(-0.25,1.883) 17(-0.75,1.883) 18(-1.25,1.883)
  oval 0.737x0.279 smd: 7(1.883,-1.25) 8(1.883,-0.75) 9(1.883,-0.25) 10(1.883,0.25) 11(1.883,0.75) 12(1.883,1.25) 19(-1.883,1.25) 20(-1.883,0.75) 21(-1.883,0.25) 22(-1.883,-0.25) 23(-1.883,-0.75) 24(-1.883,-1.25)
  rect 2.388x2.388 smd: PAD(0,0)
QFN48_7X7_PAD4_1X4_1
  oval 0.305x0.889 smd: 1(-2.75,-3.45) 2(-2.25,-3.45) 3(-1.75,-3.45) 4(-1.25,-3.45) 5(-0.75,-3.45) 6(-0.25,-3.45) 7(0.25,-3.45) 8(0.75,-3.45) 9(1.25,-3.45) 10(1.75,-3.45) 11(2.25,-3.45) 12(2.75,-3.45) 25(2.75,3.45) 26(2.25,3.45) 27(1.75,3.45) 28(1.25,3.45) 29(0.75,3.45) 30(0.25,3.45) 31(-0.25,3.45) 32(-0.75,3.45) 33(-1.25,3.45) 34(-1.75,3.45) 35(-2.25,3.45) 36(-2.75,3.45)
  oval 0.889x0.305 smd: 13(3.45,-2.75) 14(3.45,-2.25) 15(3.45,-1.75) 16(3.45,-1.25) 17(3.45,-0.75) 18(3.45,-0.25) 19(3.45,0.25) 20(3.45,0.75) 21(3.45,1.25) 22(3.45,1.75) 23(3.45,2.25) 24(3.45,2.75) 37(-3.45,2.75) 38(-3.45,2.25) 39(-3.45,1.75) 40(-3.45,1.25) 41(-3.45,0.75) 42(-3.45,0.25) 43(-3.45,-0.25) 44(-3.45,-0.75) 45(-3.45,-1.25) 46(-3.45,-1.75) 47(-3.45,-2.25) 48(-3.45,-2.75)
  rect 4.089x4.089 smd: PAD(0,0)
R0402
  rect 0.635x0.737 smd: 1(-0.5,0) 2(0.5,0)
R0805
  rect 1.041x1.397 smd: 1(-0.95,0) 2(0.95,0)
R1206
  rect 1.041x1.753 smd: 1(-1.5,0) 2(1.5,0)
SO8
  rect 0.61x2.184 smd: 1(-1.905,-2.54) 2(-0.635,-2.54) 3(0.635,-2.54) 4(1.905,-2.54) 5(1.905,2.54) 6(0.635,2.54) 7(-0.635,2.54) 8(-1.905,2.54)
SOD123-2
  rect 0.914x1.219 smd: A(1.638,0) C(-1.638,0)
SOD123F
  rect 1.194x1.194 smd: A(1.403,0) C(-1.403,0)
SOT23
  rect 1.016x1.397 smd: 1(-0.94,-1.118) 2(0.94,-1.118) 3(0,1.118)
SOT23_B
  rect 0.61x1.041 smd: 1(-0.958,-1.15) 2(0.958,-1.15) 3(0,1.15)
SWSMDIP8H91
  rect 0.762x1.27 smd: 1A(-1.905,-3.81) 1B(-1.905,3.81) 2A(-0.635,-3.81) 2B(-0.635,3.81) 3A(0.635,-3.81) 3B(0.635,3.81) 4A(1.905,-3.81) 4B(1.905,3.81)
SWSML260W236H130
  rect 3.2x0.991 smd: 1A(-3.4,-2) 1B(-3.4,2) 2A(3.4,-2) 2B(3.4,2)
TPC65D45
  round 1.651 hole 1.143: 1(0,0)
unnamed#2
  round 4.445 hole 3.175 unplated: (0,0)
WLCSP8
  round 0.254 smd: A1(-0.5,-0.5) A2(-0.5,0) A3(-0.5,0.5) B1(0,-0.5) B3(0,0.5) C1(0.5,-0.5) C2(0.5,0) C3(0.5,0.5)

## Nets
24V: C8.2(N2) C32.P C33.P C35.1 C42.2(N2) C66.1 C74.2(N2) D2.C E14.2(N2) L7.2(N2) L8.2(N2) R35.1 R91.2(N2) R105.1 TP1.1(N1) TP2.1(N1) U8.9(VIN) U8.10 U11.43 U16.10 U16.14 U16.20(VCCP2)
DGND: C1.2(N2) C2.2(N2) C3.2(N2) C4.2(N2) C5.2(N2) C6.2(N2) C7.2(N2) C8.1 C9.2(N2) C10.1 C11.2(N2) C12.1 C13.2(N2) C14.2(N2) C15.2(N2) C16.2(N2) C18.2(N2) C19.2(N2) C20.1 C21.2(N2) C26.2(N2) C27.2(N2) C28.1 C29.2(N2) C32.N(N2) C33.N(N2) C35.2(N2) C36.1 C37.1 C38.1 C39.2(N2) C40.1 C41.1 C42.1 C43.2(N2) C44.2(N2) C47.2(N2) C48.2(N2) C53.2(N2) C54.2(N2) C55.2(N2) C56.1 C57.2(N2) C58.2(N2) C63.1 C64.2(N2) C65.2(N2) C66.2(N2) C69.2(N2) C72.2(N2) C73.1 C74.1 C75.2(N2) C76.1 C77.2(N2) C78.1 C79.2(N2) C80.1 C81.2(N2) C82.2(N2) C83.N(N2) C84.N(N2) C85.2(N2) C86.2(N2) C87.2(N2) C88.2(N2) C89.2(N2) C90.2(N2) C91.2(N2) C92.2(N2) C93.N(N2) C94.2(N2) C96.2(N2) C98.2(N2) C99.2(N2) C100.1 C101.2(N2) C102.2(N2) C103.2(N2) C104.1 C106.2(N2) C108.2(N2) C109.2(N2) C110.2(N2) C115.2(N2) C116.2(N2) C117.1 C118.2(N2) C123.1 D2.A(P) D4.3 D6.3 DS1.C DS2.C DS8.C DS10.C DS12.C JP2.3(N3) P1.1 P2.2 P2.4 P2.6 P2.8 P2.10 P2.12 P2.14 P2.16 P2.18(N9) P4.1 P5.2 P5.4 P5.6 P5.8 P5.10 P5.12 P6.1 P7.1 P9.2(N2) P10.10 P13.1 P13.GND(N4) P15.2 P15.4 P15.6 P15.8 P15.10 P15.12 R18.2(N2) R19.2(N2) R23.2(N2) R25.2(N2) R28.2(N2) R49.2(N2) R50.2(N2) R57.2(N2) R58.2(N2) R60.1 R62.1 R69.1 R77.2(N2) R80.2(N2) R82.2(N2) R85.1 R106.2(N2) R107.1 R109.1 R112.1 R114.1 R116.1 S2.1A S2.2A TP5.1(N1) TP6.1(N1) TP7.1(N1) TP8.1(N1) U1.3 U2.2 U2.3 U3.3 U4.2 U4.3 U5.PAD U7.C2 U8.PAD U9.C2 U10.9 U10.PAD U11.1 U11.4 U11.10 U11.20 U11.26(VSS) U11.30 U11.32 U11.38 U11.44 U11.PAD U12.1 U12.7 U12.12 U12.20 U12.25 U12.30 U12.33 U12.37 U12.38 U12.42 U14.4 U14.7(WC_N) U15.1 U15.2 U15.3 U15.4 U15.7(WC_N) U16.11 U16.15 U16.21 U16.PAD
VDD_3V3: C56.2(N2) C63.2(N2) C84.P C88.1 C90.1 C92.1 C97.2(N2) C109.1 C110.1 E1.2(N2) E5.2(N2) E11.1 E12.2(N2) JP2.1 Q2.2(E) R16.1 R63.1 R64.1 R65.1 R71.2(N2) R72.2(N2) R73.2(N2) R83.1 R95.1 R96.1 R99.1 TP9.1(N1) U7.A2(V_POS) U9.A2(V_POS) U12.34 U12.36 U12.39 U12.48
VDD_5V: C115.1 C116.1 E3.1 L14.2(N2) R108.1 R110.1 R111.2(N2) R113.2(N2) U10.1
VIN0: R46.2(N2) U12.4
VIN1: R45.2(N2) U12.2
AD243X_ADR2/IO2/MCLK: P15.11 R11.1 U12.32 U16.1
AD243X_BCLK: R1.2(N2) R10.1 R68.1 U12.9 U12.19
AD243X_GPIO7: R14.2(N2) R117.2(N2) TP4.1(N1) U11.14
AD243X_IOVDD: C3.1 C5.1 C83.P C86.1 R17.1 R21.1 R26.1 R78.1 R86.1 R97.1 R98.2(N2) R104.2(N2) TP3.1(N1) U11.11 U11.21 U12.18
AD243X_IRQ: R8.2(N2) R17.2(N2) R20.1 U11.24
AD243X_MISO: P15.1 R100.2(N2)
AD243X_MOSI: P15.3 R101.2(N2)
AD243X_PDM_CLK: R7.2(N2) R14.1 U1.4 U2.4 U3.4 U4.4
AD243X_SCK: P15.5 R102.2(N2)
AD243X_SCL: R86.2(N2) S1.1A S1.2A U11.16
AD243X_SDA: R78.2(N2) S1.3A S1.4A(N4) U11.15
AD243X_SIO0: JP1.2 R5.2(N2) U11.5
AD243X_SIO1: C40.2(N2) R6.2(N2) R37.2(N2) R38.2(N2) U11.6
AD243X_SIO2: DS3.C P15.7 R26.2(N2) S2.1B S2.2B(N4) U11.7
AD243X_SIO3: R4.2(N2) R12.1 R67.1
AD243X_SIO4: R3.2(N2) R15.1 U12.11
AD243X_SYNC: R2.2(N2) R9.1 R59.1 U12.8 U12.16
AD243X_VOUT2: C9.1 C11.1 C13.1 E4.1 R104.1 R115.1 U11.31 U11.45
ADAU1701_MP6: JP1.3(N3) R70.1
ADAU1701_SCL: P10.1 R74.2(N2) S1.2B U12.23
ADAU1701_SDA: P10.3 R75.2(N2) S1.4B U12.22
AN: C17.2(N2) D6.1 L2.1 U11.28
AP: C17.1 D6.2(I/O2) L1.1 U11.29
BN: C25.2(N2) D4.2(I/O2) L4.1 U11.34
BP: C25.1 D4.1 L3.1 U11.33
ISENSEP: Q1.5 Q1.6 Q1.7 Q1.8 R35.2(N2) U11.42
MP1: P5.1 U12.10
MP2: P5.3 U12.29
MP3: P5.5 U12.28
MP7: P5.7 U12.14
MP8: P5.9(N9) U12.27
MP9: P5.11 U12.26
MUTE: DS6.C JP3.3(N3) R103.2(N2)
PDM_OUT2: C41.2(N2) JP1.1 R39.2(N2) R40.2(N2)
PERIPH_EN: R105.2(N2) R106.1 U10.5
SPI_CS/ADR1: P15.9(N9) R103.1 U11.22
SWP: R33.1 U11.41
UNNAMED_2_AD243XW_I16_ACM: C14.1 C15.1 U11.27
UNNAMED_2_AD243XW_I16_ADR2: R11.2(N2) U11.23
UNNAMED_2_AD243XW_I16_BCLK: R10.2(N2) U11.9
UNNAMED_2_AD243XW_I16_BCM: C10.2(N2) C12.2(N2) U11.35
UNNAMED_2_AD243XW_I16_DVDD1: C1.1 C2.1 C4.1 U11.2 U11.3 U11.47 U11.48
UNNAMED_2_AD243XW_I16_ISENSEN: R18.1 U11.36 U11.37
UNNAMED_2_AD243XW_I16_MISO: R100.1 U11.17
UNNAMED_2_AD243XW_I16_MOSI: R101.1 U11.18
UNNAMED_2_AD243XW_I16_RSTB: C81.1 R87.1 R97.2(N2) U11.25
UNNAMED_2_AD243XW_I16_SCK: R102.1 U11.19
UNNAMED_2_AD243XW_I16_SIO3: R12.2(N2) U11.12
UNNAMED_2_AD243XW_I16_SIO4: R15.2(N2) U11.13
UNNAMED_2_AD243XW_I16_SWN: R19.1 U11.39
UNNAMED_2_AD243XW_I16_SYNC: R9.2(N2) U11.8
UNNAMED_2_AD243XW_I16_VIN: C6.1 C7.1 E3.2(N2) U11.46
UNNAMED_2_CAP_I61_N1: C16.1 E4.2(N2) R22.1 R24.1 R27.1 U14.8
UNNAMED_2_CN18PODDEVEN_I182_N1: E1.1 P2.1
UNNAMED_2_CN18PODDEVEN_I182_N2: P2.3 R1.1
UNNAMED_2_CN18PODDEVEN_I182_N3: P2.5 R2.1
UNNAMED_2_CN18PODDEVEN_I182_N4: P2.7 R3.1
UNNAMED_2_CN18PODDEVEN_I182_N5: P2.9 R4.1
UNNAMED_2_CN18PODDEVEN_I182_N6: P2.11 R5.1
UNNAMED_2_CN18PODDEVEN_I182_N7: P2.13 R6.1
UNNAMED_2_CN18PODDEVEN_I182_N8: P2.15 R7.1
UNNAMED_2_CN18PODDEVEN_I182_N9: P2.17 R8.1
UNNAMED_2_DIOLED_I1_P: DS6.A(P) R95.2(N2)
UNNAMED_2_DIOLED_I49_P: DS2.A(P) R20.2(N2)
UNNAMED_2_DIOLED_I74_P: DS3.A(P) R21.2(N2)
UNNAMED_2_ICM24512_I59_E0: R22.2(N2) R23.1 U14.1
UNNAMED_2_ICM24512_I59_E1: R24.2(N2) R25.1 U14.2
UNNAMED_2_ICM24512_I59_E2: R27.2(N2) R28.1 U14.3
UNNAMED_2_ICM24512_I59_SCL: S1.1B U14.6
UNNAMED_2_ICM24512_I59_SDA: S1.3B U14.5
UNNAMED_2_NCTESTPAD_I202_N1: R87.2(N2) TP10.1(N1)
UNNAMED_3_ADLT8606V2_I35_BST: C114.1 U8.1
UNNAMED_3_ADLT8606V2_I35_INTVCC: C53.1 U8.3 U8.5
UNNAMED_3_ADLT8606V2_I35_PG: R110.2(N2) U8.8
UNNAMED_3_ADLT8606V2_I35_RT: R107.2(N2) U8.4
UNNAMED_3_ADLT8606V2_I35_SW: C114.2(N2) L14.1 U8.2
UNNAMED_3_ADLT8606V2_I35_TR: C82.1 U8.7
UNNAMED_3_CAP_I7_N1: C18.1 FL1.1 L1.2(N2)
UNNAMED_3_CAP_I8_N1: C19.1 FL1.2 L2.2(N2)
UNNAMED_3_CAP_I12_N1: C20.2(N2) C21.1 R29.2(N2) R30.1
UNNAMED_3_CAP_I14_N1: C23.1 FL1.3 R30.2(N2)
UNNAMED_3_CAP_I14_N2: C23.2(N2) L8.1 P1.3
UNNAMED_3_CAP_I15_N1: C22.1 FL1.4(N4) R29.1
UNNAMED_3_CAP_I15_N2: C22.2(N2) L7.1 P1.2
UNNAMED_3_CAP_I32_N2: C123.2(N2) P1.GND(N4)
UNNAMED_3_DIOLED_I23_P: DS4.C DS8.A(P)
UNNAMED_3_DIOLED_I24_P: DS4.A(P) R91.1
UNNAMED_3_RES_I45_N2: R108.2(N2) R109.2(N2) U8.6
UNNAMED_4_ADMAX17612X_I50_FLAGN: R115.2(N2) R117.1 U10.6
UNNAMED_4_ADMAX17612X_I50_OVLO: R113.1 R114.2(N2) U10.3
UNNAMED_4_ADMAX17612X_I50_SETI: R116.2(N2) U10.8
UNNAMED_4_ADMAX17612X_I50_UVLO: R111.1 R112.2(N2) U10.2
UNNAMED_4_CAP_I2_N1: C26.1 FL2.2 L3.2(N2)
UNNAMED_4_CAP_I3_N1: C27.1 FL2.1 L4.2(N2)
UNNAMED_4_CAP_I12_N1: C28.2(N2) C29.1 R31.2(N2) R32.1
UNNAMED_4_CAP_I14_N1: C24.1 FL2.4(N4) R32.2(N2)
UNNAMED_4_CAP_I14_N2: C24.2(N2) L12.1 P13.3
UNNAMED_4_CAP_I16_N1: C30.1 FL2.3 R31.1
UNNAMED_4_CAP_I16_N2: C30.2(N2) L11.1 P13.2
UNNAMED_4_DIOLED_I30_P: DS9.C DS12.A(P)
UNNAMED_4_DIOLED_I31_P: DS9.A(P) R36.1
UNNAMED_4_DIOSCHOTTKY_I34_N: C117.2(N2) D1.C L11.2(N2) L12.2(N2) Q1.1 Q1.2 Q1.3(S3) R34.2(N2) R36.2(N2) TP11.1(N1) U10.10
UNNAMED_4_DIOSCHOTTKY_I34_P: D1.A(P) R96.2(N2)
UNNAMED_4_RES_I22_N2: Q1.4 R33.2(N2)
UNNAMED_5_CAP_I15_N1: C36.2(N2) C37.2(N2) C38.2(N2) C39.1 E5.1 U1.2 U1.5(VDD) U2.5(VDD) U3.2 U3.5(VDD) U4.5(VDD)
UNNAMED_5_ICT3902_I1_DATA: R40.1 U4.1
UNNAMED_5_ICT3902_I2_DATA: R39.1 U3.1
UNNAMED_5_ICT3902_I3_DATA: R38.1 U2.1
UNNAMED_5_ICT3902_I4_DATA: R37.1 U1.1
UNNAMED_7_AD8606_I11_INV: C46.2(N2) C52.P U7.A1 U7.B1
UNNAMED_7_AD8606_I11_NINV: C44.1 R44.2(N2) U7.C1
UNNAMED_7_AD8606_I21_INV: C45.2(N2) C51.P U7.A3 U7.B3
UNNAMED_7_AD8606_I21_NINV: C43.1 R43.2(N2) U7.C3
UNNAMED_7_AD8606_I58_INV: C60.2(N2) C62.P U9.A1 U9.B1
UNNAMED_7_AD8606_I58_NINV: C58.1 R54.2(N2) U9.C1
UNNAMED_7_AD8606_I66_INV: C59.2(N2) C61.P U9.A3 U9.B3
UNNAMED_7_AD8606_I66_NINV: C57.1 R53.2(N2) U9.C3
UNNAMED_7_CAP_I20_N1: C46.1 R42.2(N2) R44.1
UNNAMED_7_CAP_I22_N1: C45.1 R41.2(N2) R43.1
UNNAMED_7_CAP_I29_N1: C48.1 C50.2(N2) E10.2(N2)
UNNAMED_7_CAP_I34_N1: C47.1 C49.2(N2) E9.2(N2)
UNNAMED_7_CAP_I38_N1: C55.1 P6.2 R48.2(N2) R50.1
UNNAMED_7_CAP_I46_N1: C54.1 P6.3(N3) R47.2(N2) R49.1
UNNAMED_7_CAP_I60_N1: C65.1 P7.2 R56.2(N2) R58.1
UNNAMED_7_CAP_I64_N1: C60.1 R52.2(N2) R54.1
UNNAMED_7_CAP_I67_N1: C59.1 R51.2(N2) R53.1
UNNAMED_7_CAP_I73_N1: C64.1 P7.3(N3) R55.2(N2) R57.1
UNNAMED_7_CAP_I83_N1: C49.1 R45.1
UNNAMED_7_CAP_I84_N1: C50.1 R46.1
UNNAMED_7_CAPP_I23_N2: C52.N(N2) R48.1
UNNAMED_7_CAPP_I25_N2: C51.N(N2) R47.1
UNNAMED_7_CAPP_I68_N2: C62.N(N2) R56.1
UNNAMED_7_CAPP_I69_N2: C61.N(N2) R55.1
UNNAMED_7_CN3P_I18_N2: E10.1 P4.2
UNNAMED_7_CN3P_I18_N3: E9.1 P4.3(N3)
UNNAMED_10_CAP_I3_N1: C75.1 L5.2(N2) P16.1(N1)
UNNAMED_10_CAP_I5_N1: C68.1 R60.2(N2)
UNNAMED_10_CAP_I7_N1: C69.1 R61.2(N2)
UNNAMED_10_CAP_I9_N2: C76.2(N2) L6.2(N2) P17.1(N1)
UNNAMED_10_CAP_I12_N1: C79.1 U16.16
UNNAMED_10_CAP_I14_N1: C77.1 L9.2(N2) P18.1(N1)
UNNAMED_10_CAP_I15_N2: C78.2(N2) L10.2(N2) P19.1(N1)
UNNAMED_10_CAP_I19_N1: C70.1 U16.18
UNNAMED_10_CAP_I19_N2: C70.2(N2) L6.1 R61.1 U16.19
UNNAMED_10_CAP_I21_N1: C31.1 U16.22
UNNAMED_10_CAP_I21_N2: C31.2(N2) C68.2(N2) L5.1 U16.23
UNNAMED_10_CAP_I24_N2: C73.2(N2) U16.17
UNNAMED_10_CAP_I25_N1: C71.1 R62.2(N2)
UNNAMED_10_CAP_I25_N2: C67.1 C71.2(N2) L9.1 U16.13
UNNAMED_10_CAP_I26_N2: C67.2(N2) U16.12
UNNAMED_10_CAP_I29_N1: C34.1 L10.1 R76.1 U16.8
UNNAMED_10_CAP_I29_N2: C34.2(N2) U16.9
UNNAMED_10_CAP_I39_N1: C72.1 R76.2(N2)
UNNAMED_10_CAP_I55_N1: C118.1 R99.2(N2) U16.6
UNNAMED_10_CN3P_I53_N2: JP2.2 R63.2(N2) U16.5
UNNAMED_10_CN3P_I54_N1: JP3.1 R65.2(N2)
UNNAMED_10_CN3P_I54_N2: JP3.2 R66.1
UNNAMED_10_DIOLED_I30_N: DS11.C U16.24
UNNAMED_10_DIOLED_I30_P: DS11.A(P) R64.2(N2)
UNNAMED_10_ICBD28623MUV_I28_BCLK: R68.2(N2) U16.3
UNNAMED_10_ICBD28623MUV_I28_LRCLK: R59.2(N2) U16.4
UNNAMED_10_ICBD28623MUV_I28_MUTEX: R66.2(N2) U16.7
UNNAMED_10_ICBD28623MUV_I28_SDATA: R67.2(N2) U16.2
UNNAMED_11_ADAU1701_I48_ADCRES: R69.2(N2) U12.3
UNNAMED_11_ADAU1701_I48_CM: C89.1 C91.1 U12.40
UNNAMED_11_ADAU1701_I48_DVDD: C93.P C94.1 C96.1 Q2.3 U12.13 U12.24
UNNAMED_11_ADAU1701_I48_FILTA: C85.1 C87.1 U12.47
UNNAMED_11_ADAU1701_I48_FILTD: C98.1 C99.1 U12.41
UNNAMED_11_ADAU1701_I48_MP6: R70.2(N2) U12.15
UNNAMED_11_ADAU1701_I48_PLLLF: C95.1 C97.1 U12.35
UNNAMED_11_ADAU1701_I48_RESETB: C80.2(N2) R88.1 R98.1 U12.5
UNNAMED_11_ADAU1701_I48_SELFBOOT: P9.1 R73.1 U12.6
UNNAMED_11_ADAU1701_I48_VDRIVE: Q2.1 R72.1 U12.17
UNNAMED_11_CAP_I20_N2: C95.2(N2) R71.1
UNNAMED_11_CAP_I41_N2: C100.2(N2) E11.2(N2) U15.8
UNNAMED_11_CN10P_I109_N4: DS5.A(P) P10.4
UNNAMED_11_DIOLED_I121_N: DS5.C R77.1
UNNAMED_11_ICM24512_I37_SCL: R74.1 U15.6
UNNAMED_11_ICM24512_I37_SDA: R75.1 U15.5
UNNAMED_11_NCTESTPAD_I134_N1: R88.2(N2) TP12.1(N1)
UNNAMED_12_ADLT8609_I124_BST: C105.2(N2) U5.1
UNNAMED_12_ADLT8609_I124_EN: R79.1 R80.1 U5.10
UNNAMED_12_ADLT8609_I124_FB: C107.2(N2) R84.2(N2) R85.2(N2) U5.6
UNNAMED_12_ADLT8609_I124_INTVCC: C103.1 R81.1 U5.3
UNNAMED_12_ADLT8609_I124_PG: R83.2(N2) U5.8
UNNAMED_12_ADLT8609_I124_RT: R82.1 U5.4
UNNAMED_12_ADLT8609_I124_SW: C105.1 L13.1 U5.2
UNNAMED_12_ADLT8609_I124_SYNC: R81.2(N2) U5.5
UNNAMED_12_ADLT8609_I124_TR: C104.2(N2) U5.7
UNNAMED_12_ADLT8609_I124_VIN: C101.1 C102.1 E14.1 R79.2(N2) R151.1 U5.9(VIN)
UNNAMED_12_CAP_I111_N1: C106.1 C107.1 C108.1 E12.1 L13.2(N2) R84.1
UNNAMED_12_DIOLED_I105_P: DS1.A(P) R16.2(N2)
UNNAMED_12_DIOLED_I136_P: DS10.A(P) R151.2(N2)
VOUT0: R41.1 U12.46
VOUT1: R42.1 U12.45
VOUT2: R51.1 U12.44
VOUT3: R52.1 U12.43(VOUT3)
VSENSEP: R34.1 U11.40

Pads without a net: P10 2 5 6 7 8 9; U10 4 7; U12 21 31

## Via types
v1: diameter 0.508, hole 0.254, TOP to BOTTOM, 1313 vias

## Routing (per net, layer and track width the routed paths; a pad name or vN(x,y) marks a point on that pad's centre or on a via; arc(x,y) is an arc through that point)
24V: length 63.4
  TOP w0.254: C42.2 82.3,45.75 U8.9 ; U11.43 48.77,52.82 48.85,52.9 ; U8.10 v1(81.15,44.4) ; v1(55.12,114.94) 54.92,114.74 U16.10 ; U16.14 53.07,117.11 v1(52.83,117.35) ; v1(49.62,114.94) 49.66,114.94 49.96,115.24 U16.20
  TOP w0.508: D2.C 82.16,48.39 R105.1 ; v1(55.12,114.94) v1(55.63,114.94) ; v1(52.83,117.35) v1(52.83,117.86) ; v1(49.62,114.94) v1(49.1,114.94) ; v1(49.03,53.08) 48.85,52.9 ; v1(68.01,34.78) v1(68.01,34.27) v1(68.52,34.27) v1(68.52,34.78) v1(68.52,35.28) v1(68.01,35.28) v1(68.01,34.78)
  TOP w1.016: E14.2 TP2.1
  L4_PWR w0.508: 7.2,39.88 TP2.1 ; TP2.1 9.56,39.88 ; TP2.1 8.38,38.7 ; TP1.1 23.24,25.57 ; TP1.1 22.06,24.38 ; TP1.1 23.24,23.2 ; TP1.1 24.42,24.38
  BOTTOM w0.406: R35.1 67.25,43.79 59.38,51.66 51.29,51.66 50.8,52.15 50.8,52.92 C8.2
  BOTTOM w0.508: v1(71.42,30.39) v1(71.42,30.9) v1(70.92,30.9) ; v1(71.42,30.39) v1(71.42,29.88) ; v1(71.42,30.39) v1(70.92,30.39) ; v1(70.41,30.39) v1(70.92,30.39) ; v1(70.41,30.39) v1(70.41,29.88) ; v1(70.41,30.39) v1(70.41,30.9) v1(70.92,30.9) ; v1(70.92,30.39) v1(70.92,29.88) ; v1(70.92,30.39) v1(70.92,30.9) ; v1(70.41,29.88) v1(70.41,29.37) v1(70.92,29.37) ; v1(70.41,29.88) v1(70.92,29.88) ; v1(70.92,29.88) v1(71.42,29.88) ; v1(70.92,29.88) v1(70.92,29.37) ; v1(71.42,29.88) v1(71.42,29.37) v1(70.92,29.37) ; C8.2 50.12,53.08 v1(49.03,53.08)
  vias: v1(20.69,30.38) v1(20.69,29.87) v1(20.69,29.36) v1(20.69,28.85) v1(20.69,28.34) v1(20.69,27.84) v1(21.2,30.38) v1(21.2,29.87) v1(21.2,29.36) v1(21.2,28.85) v1(21.2,28.34) v1(21.2,27.84) v1(21.71,30.38) v1(21.71,29.87) v1(21.71,29.36) v1(21.71,28.85) v1(21.71,28.34) v1(21.71,27.84) v1(81.66,49.78) v1(81.66,49.15) v1(82.3,49.78) v1(82.3,49.15)
